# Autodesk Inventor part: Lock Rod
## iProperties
Shininess: 64.0
Length Units: 11272
Angle Units: 11279
Time Units: 11290
Mass Units: 11286
Length Display Precision: 3
Angle Display Precision: 2
Compacted: True
Part Number: Lock Rod
Document SubType Name: Modeling
Created: 2003-10
Designer: jpittman
Manufacturer: Standard
Standards Organization: Custom
Density: 0.0
Volumn: 0.0
Area: 0.0
PropertySet Name: Model Information
Control State: 0
Master: False
Checked Out: False
Author: jpittman
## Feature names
1. Extrusion1
